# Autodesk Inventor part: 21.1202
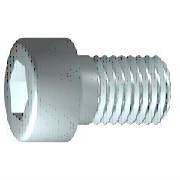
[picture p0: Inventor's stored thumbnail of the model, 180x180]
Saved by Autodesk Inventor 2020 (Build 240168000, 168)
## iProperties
Created: 2006-02
Part Number: 21.1202
Material: Steel, Mild
Description: M8 x 20 SHCS
Document SubType Name: Modeling
Standard: DIN 7984
Designer: Andy Moles
Standards Organization: DIN
Language: en-US
Size Designation: M8 x 20
Categories: <MemberInstance><Categories><Category DisplayName="Fasteners" InternalName="e4da775c-781d-43d5-af7c-5136215cf5a6" Mnemonic="FSTN"><Category DisplayName="Bolts"
Mass: 12.2474 g
Surface Area: 10.1767 cm^2
Volume: 1.56018 cm^3
Density: 7.85 g/cm^3
Vendor: S
Appearance: Zinc
Author: Andy Moles
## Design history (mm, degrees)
sketch "Sketch1"
  geometry: L1 (0.467, 0)-(20, 0); L2 (20, 0)-(20, 4); L3 (20, 4)-(1, 4); L4 (1, 4)-(0.233, 4); L5 (0.233, 4)-(0, 4); L6 (0, 4)-(0, 6.5); L7 (0, 6.5)-(-5, 6.5); L8 (-5, 6.5)-(-5, 2.887); L9 (-5, 2.887)-(-1.2, 2.887); L10 (-1.2, 2.887)-(0.467, 0); L11 (-7.5, 0)-(27.5, 0) reference; L12 (0, -0.65)-(0, 8.45) reference; L13 (1, 4)-(0, 4)
  constraints: 22 end point, 6 parallel, 2 collinear, 2 perpendicular, 1 horizontal, 1 point on line
  dimensions: "d1" = 19 distance from line of L3.end L2 (= GEL); "d2" = 0.76691 distance of L4.end L3.end (computed from GAL); "d3" = 5 distance between parallel lines of L8 L6 (= KOH); "d4" = 3.8 distance of L8.end L9.end (= INTI); "d5" = 60 deg angle of L10 L1; "d6" = 8 diameter of L3 L1 (= GD); "d7" = 8 diameter of L5 L1 (= BDM); "d8" = 5.7735 diameter of L9 L1 (= 1.1547 x SW); "d9" = 13 diameter of L7 L1 (= KOD); "d26" = 20 distance between parallel lines of L12 L2 (= NLG)
revolve "Body" sketch "Sketch1" stored, may be unused: angle "d10" = 90 deg
sketch "Sketch2"
  geometry: L1 (0, -7.8)-(0, 10.4) reference; L2 (-7.8, 0)-(10.4, 0) reference; L3 (2.887, 0)-(1.443, -2.5); L4 (1.443, -2.5)-(-1.443, -2.5); L5 (-1.443, -2.5)-(-2.887, 0); L6 (-2.887, 0)-(-1.443, 2.5); L7 (-1.443, 2.5)-(1.443, 2.5); L8 (1.443, 2.5)-(2.887, 0); 2 further points
  constraints: 12 end point, 1 coincident, 1 horizontal alignment, 1 point on line, 12 other
extrude "Slot" join sketch "Sketch2" stored distance "d11" = 10; taper "d12" = 0 deg
workplane "Work Plane1"
body "Solid1"
fillet "Fillet1" dims "d17" = 0.8 (= RR)
feature "Thread" dims "d13" = 20, "d14" = 0
chamfer "Chamfer1" distance "d15" = 0.76681 (= -0.5 x SPD + 0.5 x GD); stored, may be unused: second distance "d16" = 0.76681 (= GUL), angle "d27" = 45 deg
other parameters: "GD" = 8 (= NND) [user parameter; used in 2 equation terms], "NLG" = 20 [user parameter; used in 1 equation term], "GEL" = 19 [user parameter; used in 1 equation term], "KOD" = 13 [user parameter; used in 1 equation term], "KOH" = 5 [user parameter; used in 1 equation term], "INTI" = 3.8 [user parameter; used in 1 equation term], "GAL" = 0.76681 (= 0.61345 x PTC) [user parameter; used in 1 equation term], "GUL" = 0.76681 (= 0.61345 x PTC) [user parameter; used in 1 equation term], "BDM" = 8 (= NND) [user parameter; used in 1 equation term], "SW" = 5 [user parameter; used in 2 equation terms], "RR" = 0.8 [user parameter; used in 1 equation term], "SPD" = 6.46637 (= NND - 1.2269 x PTC) [user parameter; used in 1 equation term], "d19" = 0, "d28" = 0, "d29" = 0, "TOA" = 30 deg [user parameter], "GD1" = 6.46637 (= THREADDIA - 1.2269 x PTC) [user parameter], "THREADDIA" = 8 [user parameter; used in 1 equation term], "FAWI" = 45 deg [user parameter], "ANG" = 120 deg [user parameter], "TPU" = 8 (computed from PTC) [user parameter], "PTC" = 1.25 [user parameter; used in 5 equation terms], "NND" = 8 [user parameter; used in 3 equation terms], "E0" = 5.775 (= 1.155 x SW) [user parameter]
